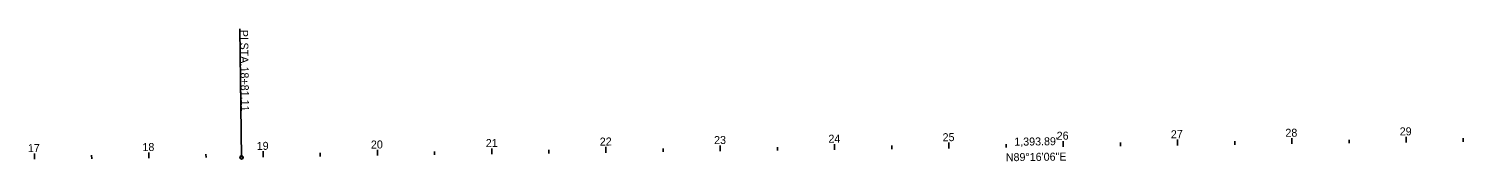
# Model space of a CAD drawing. Extents: x 1805035 to 1810276, y 297762 to 303660.
# Drawn here: x 1806359 to 1807614, y 298342 to 298458 of the extents above; entities that cross this region are included whole.
import ezdxf

# ---------------------------------------------------------------- set-up
doc = ezdxf.new("R2010")
doc.units = 0
for name, color, linetype in [('GE_P_Alignment_100_Bearings', 7, 'Continuous'), ('GE_P_Alignment_100_Cardinal_Points', 7, 'Continuous'), ('GE_P_Alignment_100_Distances', 7, 'Continuous'), ('GE_P_Alignment_100_Stations', 7, 'Continuous')]:
    doc.layers.add(name, color=color, linetype=linetype)

msp = doc.modelspace()

# ---------------------------------------------------------------- linework, layer by layer
at = {"layer": 'GE_P_Alignment_100_Cardinal_Points'}
msp.add_line((1806545.4, 298345.4), (1806543.9, 298457.9), dxfattribs=at)
msp.add_circle((1806545.4, 298345.4), 1.5, dxfattribs=at)
at = {"layer": 'GE_P_Alignment_100_Stations'}
for p, q in [((1806764.3, 298348.2), (1806764.2, 298353.2)), ((1806864.2, 298349.5), (1806864.2, 298354.5)), ((1806914.2, 298350.2), (1806914.2, 298353.1)), ((1806964.2, 298350.8), (1806964.2, 298355.8)), ((1807014.2, 298351.4), (1807014.2, 298354.4)), ((1807064.2, 298352.1), (1807064.2, 298357.1)), ((1807114.2, 298352.7), (1807114.2, 298355.7)), ((1807164.2, 298353.3), (1807164.2, 298358.3)), ((1807214.2, 298354), (1807214.2, 298357)), ((1807264.2, 298354.6), (1807264.1, 298359.6)), ((1807314.2, 298355.3), (1807314.2, 298358.3)), ((1807364.2, 298355.9), (1807364.1, 298360.9)), ((1807414.2, 298356.5), (1807414.2, 298359.5)), ((1807464.2, 298357.2), (1807464.1, 298362.2)), ((1807514.2, 298357.8), (1807514.2, 298360.8)), ((1807564.2, 298358.4), (1807564.1, 298363.4)), ((1807614.2, 298359.1), (1807614.1, 298362.1)), ((1806364.3, 298343.8), (1806364.2, 298348.8)), ((1806414.3, 298344.2), (1806414.2, 298347.2)), ((1806464.3, 298344.7), (1806464.2, 298349.7)), ((1806514.3, 298345.2), (1806514.2, 298348.2)), ((1806564.3, 298345.7), (1806564.2, 298350.7)), ((1806614.3, 298346.3), (1806614.2, 298349.3)), ((1806664.3, 298347), (1806664.2, 298352)), ((1806714.3, 298347.6), (1806714.2, 298350.6)), ((1806814.2, 298348.9), (1806814.2, 298351.9))]:
    msp.add_line(p, q, dxfattribs=at)

# ---------------------------------------------------------------- texts
at = {"layer": 'GE_P_Alignment_100_Bearings'}
msp.add_text('N89°16\'06"E', height=7, rotation=0.7316, dxfattribs=at).set_placement((1807214, 298342))
at = {"layer": 'GE_P_Alignment_100_Cardinal_Points'}
for s, p in [('PI', (1806544.1, 298456.9)), (' STA. ', (1806544.2, 298448.4)), ('18+81.11', (1806544.5, 298424.8))]:
    msp.add_text(s, height=7, rotation=270.7316, dxfattribs=at).set_placement(p)
at = {"layer": 'GE_P_Alignment_100_Distances'}
msp.add_text("1,393.89'", height=7, rotation=0.7316, dxfattribs=at).set_placement((1807221.4, 298355.6))
at = {"layer": 'GE_P_Alignment_100_Stations'}
for s, rotation, p in [('24', 0.7316, (1807058.8, 298358.2)), ('25', 0.7316, (1807158.7, 298359.5)), ('26', 0.7316, (1807258.5, 298360.8)), ('27', 0.7316, (1807358.4, 298362.1)), ('28', 0.7316, (1807458.6, 298363.4)), ('29', 0.7316, (1807558.6, 298364.6)), ('17', 0.5335, (1806358.5, 298350)), ('18', 0.5335, (1806458.7, 298350.9)), ('19', 0.7316, (1806558.7, 298351.9)), ('20', 0.7316, (1806658.6, 298353.1)), ('21', 0.7316, (1806759.1, 298354.4)), ('22', 0.7316, (1806858.8, 298355.7)), ('23', 0.7316, (1806958.8, 298357))]:
    msp.add_text(s, height=7, rotation=rotation, dxfattribs=at).set_placement(p)

doc.saveas('drawing.dxf')
